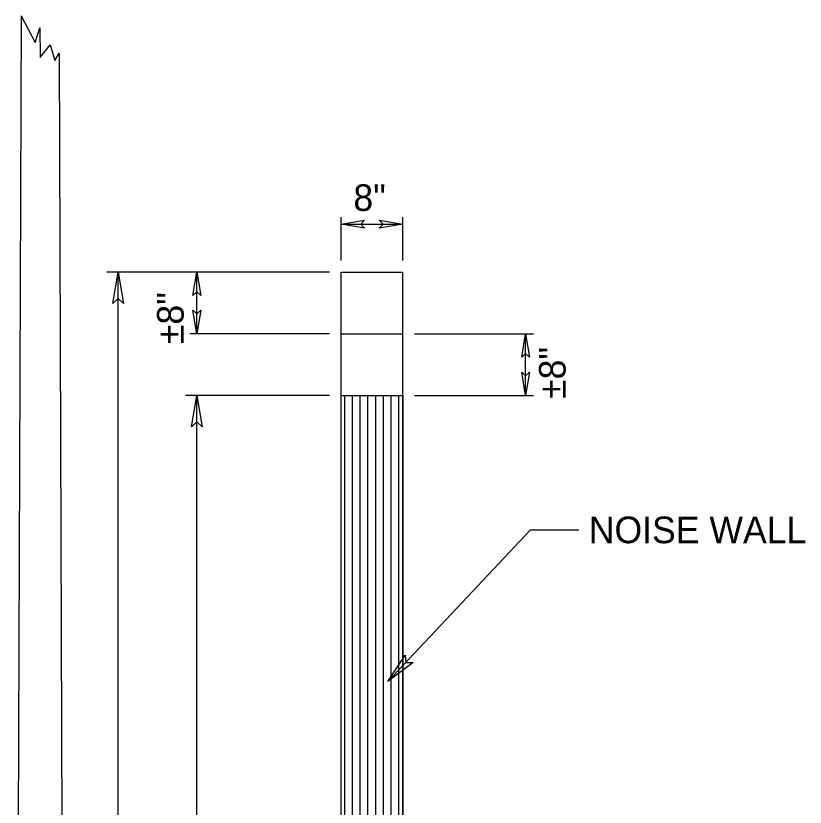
# Model space of a CAD drawing. Extents: x 99836 to 115004, y 99786 to 102182.
# Drawn here: x 114172.5 to 114528.2, y 101226.5 to 101583 of the extents above; entities that cross this region are included whole.
import ezdxf

# ---------------------------------------------------------------- set-up
doc = ezdxf.new("R2010")
doc.units = 0
doc.layers.add('Border Organizer Shape', color=7, linetype='Continuous')

msp = doc.modelspace()

# ---------------------------------------------------------------- linework, layer by layer
at = {"layer": 'Border Organizer Shape'}
for p, q in [((114174.8, 101582.99), (114172.45, 100924.3)), ((114174.8, 101582.99), (114181.22, 101570.95)), ((114181.22, 101570.95), (114183.3, 101577.57)), ((114183.3, 101577.57), (114183.48, 101564.15)), ((114183.48, 101564.15), (114188, 101569.9)), ((114188, 101569.9), (114190.09, 101562.93)), ((114190.09, 101562.93), (114191.92, 101566.21)), ((114191.92, 101566.21), (114194.21, 100924.3)), ((114319.06, 101472.76), (114319.06, 101492.29)), ((114346.86, 101472.76), (114346.86, 101492.29)), ((114319.06, 101489.09), (114346.86, 101489.09)), ((114313.85, 101467.55), (114213.4, 101467.55)), ((114218.61, 100997.87), (114218.61, 101467.55)), ((114313.85, 101467.55), (114248.88, 101467.55)), ((114254.09, 101439.75), (114254.09, 101467.55)), ((114319.06, 100612.67), (114319.06, 101467.55)), ((114319.06, 101467.55), (114346.86, 101467.55)), ((114346.86, 101022.73), (114346.86, 101467.55)), ((114313.85, 101439.75), (114250.91, 101439.75)), ((114319.06, 101439.75), (114346.86, 101439.75)), ((114352.08, 101439.75), (114405.74, 101439.75)), ((114402.24, 101411.95), (114402.24, 101439.75)), ((114313.85, 101411.95), (114248.88, 101411.95)), ((114254.09, 100997.87), (114254.09, 101411.95)), ((114319.06, 101411.95), (114346.86, 101411.95)), ((114320.75, 100612.67), (114320.75, 101411.95)), ((114324.23, 100612.67), (114324.23, 101411.95)), ((114327.7, 100612.67), (114327.7, 101411.95)), ((114331.18, 100612.67), (114331.18, 101411.95)), ((114334.65, 100612.67), (114334.65, 101411.95)), ((114338.13, 100612.67), (114338.13, 101411.95)), ((114341.6, 100612.67), (114341.6, 101411.95)), ((114345.08, 100612.67), (114345.08, 101411.95)), ((114352.08, 101411.95), (114405.74, 101411.95)), ((114340.08, 101283.05), (114404.43, 101351.4)), ((114404.43, 101351.4), (114426.22, 101351.4))]:
    msp.add_line(p, q, dxfattribs=at)
for points in [[(114329.64, 101487.29), (114319.06, 101489.09), (114329.64, 101490.88), (114327.98, 101489.09)], [(114336.29, 101490.88), (114346.86, 101489.09), (114336.29, 101487.29), (114337.95, 101489.09)], [(114216.22, 101453.45), (114218.61, 101467.55), (114221.01, 101453.45), (114218.61, 101455.66)], [(114252.3, 101456.97), (114254.09, 101467.55), (114255.89, 101456.97), (114254.09, 101458.63)], [(114255.89, 101450.32), (114254.09, 101439.75), (114252.3, 101450.32), (114254.09, 101448.66)], [(114400.45, 101429.17), (114402.24, 101439.75), (114404.04, 101429.17), (114402.24, 101430.83)], [(114404.04, 101422.52), (114402.24, 101411.95), (114400.45, 101422.52), (114402.24, 101420.86)], [(114251.7, 101397.84), (114254.09, 101411.95), (114256.49, 101397.84), (114254.09, 101400.06)], [(114319.06, 101411.95), (114346.86, 101411.95), (114346.86, 100612.67), (114319.06, 100612.67)], [(114351.49, 101291.67), (114340.08, 101283.05), (114348, 101294.96), (114348.23, 101291.7)]]:
    msp.add_lwpolyline(points, close=True, dxfattribs=at)

# ---------------------------------------------------------------- texts
for s, p in [('8"', (114324.59, 101495.09)), (' NOISE WALL', (114426.22, 101345.4))]:
    msp.add_text(s, height=12, dxfattribs=at).set_placement(p)
for p in [(114248.09, 101435.08), (114420.24, 101410.39)]:
    msp.add_text('±8"', height=12, rotation=90, dxfattribs=at).set_placement(p)

doc.saveas('drawing.dxf')
